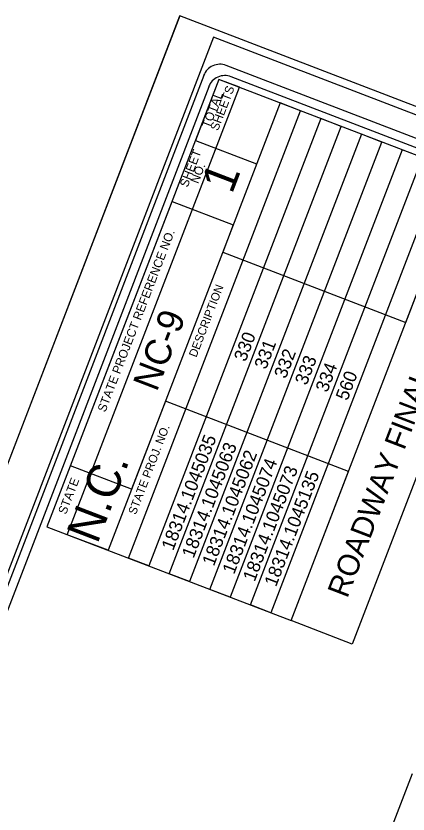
# Model space of a CAD drawing. Extents: x 1015221 to 1064345, y 619216 to 647967.
# Drawn here: x 1019300 to 1021098, y 644303 to 647967 of the extents above; entities that cross this region are included whole.
import ezdxf

# ---------------------------------------------------------------- set-up
doc = ezdxf.new("R2010")
doc.units = 0
for name, color, linetype in [('Prop DSN Text', 7, 'Continuous'), ('Sheet Cutting Line CELL', 7, 'Continuous'), ('Sheet Data Field CELL', 7, 'Continuous'), ('Sheet Plot Border Inside CELL', 7, 'Continuous'), ('Sheet Plot Border Outside CELL', 7, 'Continuous'), ('Sheet Title CELL', 7, 'Continuous')]:
    doc.layers.add(name, color=color, linetype=linetype)

msp = doc.modelspace()

# ---------------------------------------------------------------- linework, layer by layer
at = {"layer": 'Prop DSN Text'}
msp.add_lwpolyline([(1023225.6, 640401.1), (1020495.1, 642865.6), (1021119.1, 644489.5)], dxfattribs=at)
at = {"layer": 'Sheet Cutting Line CELL'}
msp.add_line((1015220.5, 635391.3), (1020052.2, 647967.1), dxfattribs=at)
at = {"layer": 'Sheet Plot Border Inside CELL'}
msp.add_lwpolyline([(1023304.8, 632396.8), (1028086.2, 644841.8), (1020206.9, 647869.1), (1015425.5, 635424)], close=True, dxfattribs=at)
at = {"layer": 'Sheet Plot Border Outside CELL'}
msp.add_lwpolyline([(1020052.2, 647967.1), (1015220.5, 635391.3), (1023435, 632235.3), (1028266.7, 644811.1)], close=True, dxfattribs=at)
at = {"layer": 'Sheet Title CELL'}
for points in [[(1027956.5, 644784.5), (1020264.8, 647739.7)], [(1020161.5, 647693.8), (1015914.9, 636641.4)], [(1021258.3, 647280.9), (1020469.2, 645227.3), (1020376, 645263.1), (1021165, 647316.7), (1021071.6, 647352.6), (1020282.6, 645299.1), (1020189.2, 645334.9), (1020978.2, 647388.5), (1020884.8, 647424.4), (1020095.8, 645370.7), (1020002.6, 645406.6), (1020791.5, 647460.2), (1020698.2, 647496.1), (1019909.2, 645442.4), (1019815.9, 645478.3), (1020604.9, 647531.9), (1020511.4, 647567.8), (1019722.4, 645514.2), (1019535.7, 645585.9), (1020324.8, 647639.6), (1020231.4, 647675.4), (1019442.5, 645621.7), (1020562.6, 645191.4), (1020825.6, 645875.8), (1019985.5, 646198.6), (1019830.1, 645794.2), (1019550, 645901.8), (1020016.3, 647115.4), (1020296.3, 647007.8), (1020248.3, 646883), (1021088.5, 646560.3), (1021351.6, 647245.1), (1020231.4, 647675.4), (1020123.8, 647395.4), (1020403.9, 647287.9)], [(1026523.4, 645292.3), (1020287.7, 647688.1)], [(1020184.4, 647642.1), (1016110.2, 637037.9)], [(1020562.6, 645191.4), (1021351.6, 647245.1)]]:
    msp.add_lwpolyline(points, dxfattribs=at)
msp.add_lwpolyline([(1020562.6, 645191.4), (1021351.6, 647245.1), (1021631.6, 647137.5), (1020842.6, 645083.8)], close=True, dxfattribs=at)
for centre in [(1020235.7, 647665.3), (1020258.7, 647613.6)]:
    msp.add_arc(centre, 80, 68.983, 158.983, dxfattribs=at)

# ---------------------------------------------------------------- texts
at = {"layer": 'Prop DSN Text'}
msp.add_text('ROADWAY FINAL PLAN SET', height=100, rotation=68.983, dxfattribs=at).set_placement((1020819.5, 645290.4))
at = {"layer": 'Sheet Data Field CELL'}
for s, height, p in [('NC-9', 120, (1019945.9, 646238.3)), ('330', 60, (1020353.4, 646376.6)), ('331', 60, (1020446.9, 646341.1)), ('332', 60, (1020537.7, 646298.9)), ('333', 60, (1020633.2, 646268.6)), ('334', 60, (1020727.7, 646235.5)), ('560', 60, (1020820.2, 646197.5)), ('18314.1045035', 60, (1020021.1, 645509.5)), ('18314.1045063', 60, (1020114.6, 645474.1)), ('18314.1045062', 60, (1020207.9, 645438.3)), ('18314.1045074', 60, (1020300.6, 645400.6)), ('18314.1045073', 60, (1020394.8, 645366.9)), ('18314.1045135', 60, (1020493, 645343.5))]:
    msp.add_text(s, height=height, rotation=68.983, dxfattribs=at).set_placement(p)
at = {"layer": 'Sheet Title CELL'}
for s, height, p in [('SHEETS', 40, (1020226.8, 647437.1)), ('TOTAL', 40, (1020188.5, 647448.9)), ('SHEET', 40, (1020087.4, 647177.6)), ('NO.', 40, (1020136.1, 647194.4)), ('1', 154.8, (1020290.6, 647145.8)), ('STATE PROJECT REFERENCE NO.', 39.998, (1019710.1, 646145.4)), ('DESCRIPTION', 38.4, (1020127.5, 646397.3)), ('STATE PROJ. NO.', 38.4, (1019849.7, 645674.8)), ('N.C.', 154.8, (1019673.4, 645539.4)), ('STATE', 40, (1019529.7, 645676.1))]:
    msp.add_text(s, height=height, rotation=68.983, dxfattribs=at).set_placement(p)

doc.saveas('drawing.dxf')
